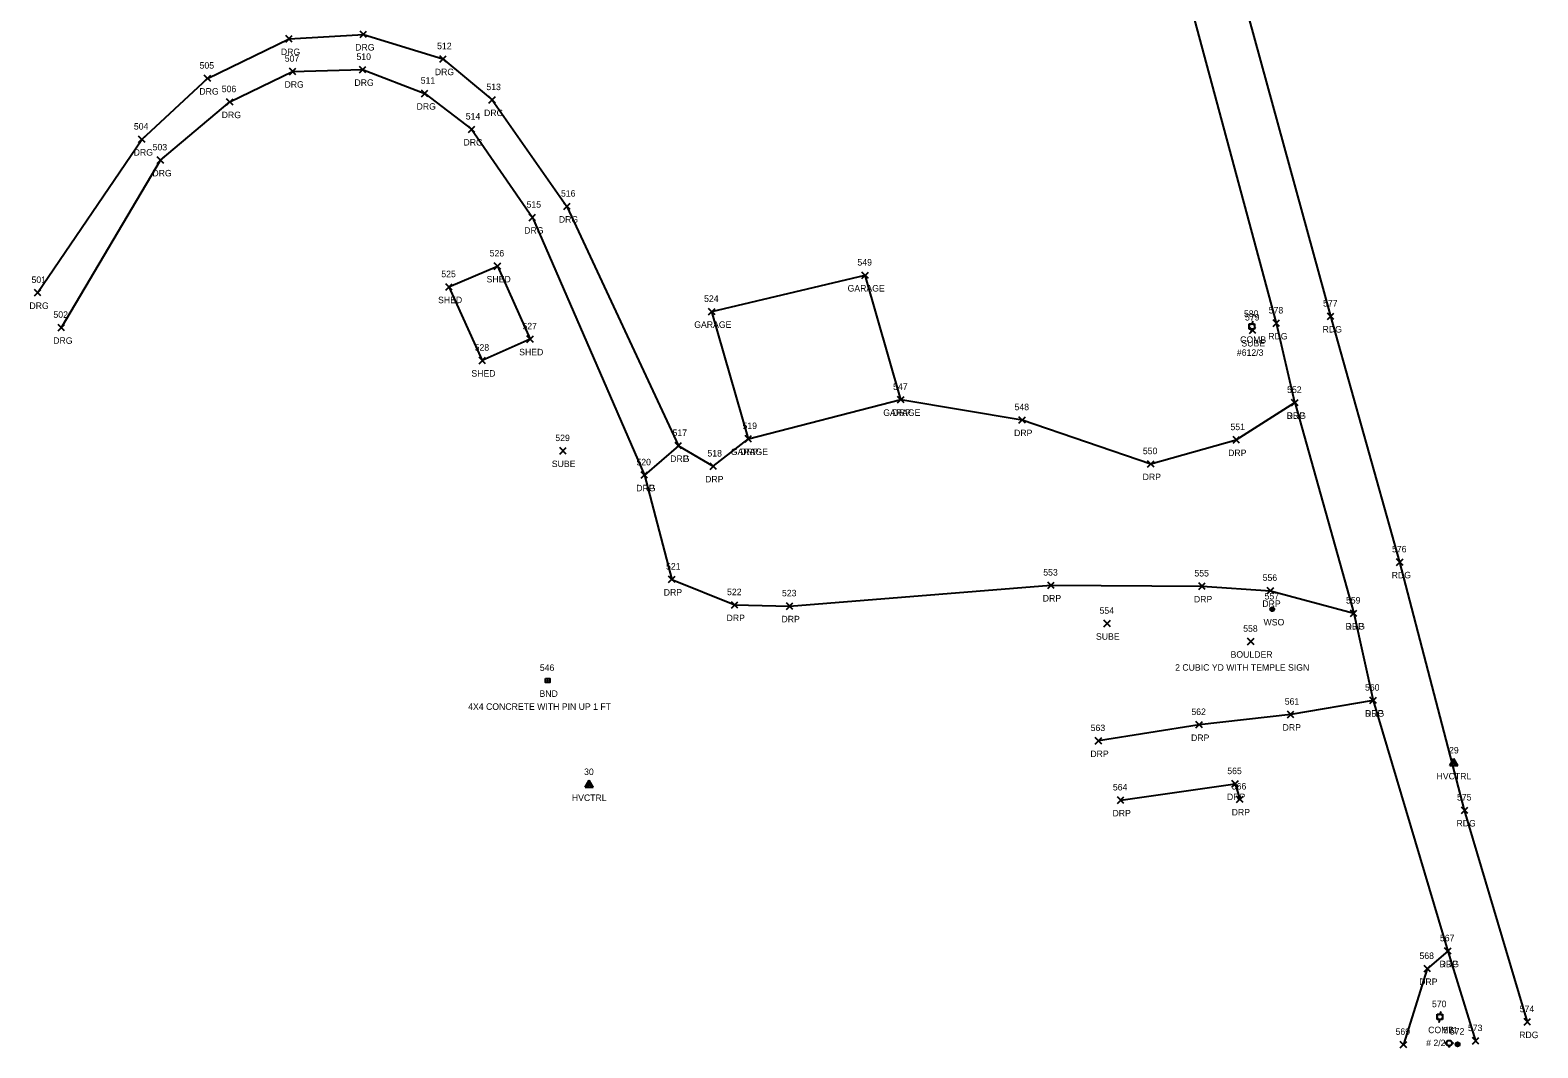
# Model space of a CAD drawing. Extents: x 1845178 to 1850791, y 714586 to 722436.
# Drawn here: x 1850260.9 to 1850725.1, y 716482.1 to 716795.6 of the extents above; entities that cross this region are included whole.
import ezdxf

# ---------------------------------------------------------------- set-up
doc = ezdxf.new("R2010")
doc.units = 0
for name, color, linetype in [('C_A', 7, 'Continuous'), ('C_I', 7, 'Continuous'), ('CPSM', 7, 'Continuous'), ('L_A', 7, 'Continuous'), ('L_C', 7, 'Continuous'), ('L_I', 7, 'Continuous'), ('L_TIC', 7, 'Continuous'), ('LBC', 7, 'Continuous'), ('Level 18', 7, 'Continuous'), ('M_A', 7, 'Continuous'), ('M_C', 7, 'Continuous'), ('M_I', 7, 'Continuous'), ('P_A', 7, 'Continuous'), ('P_I', 7, 'Continuous'), ('P_TIC', 7, 'Continuous'), ('PEU', 7, 'Continuous'), ('R_A', 7, 'Continuous'), ('R_I', 7, 'Continuous'), ('R_TIC', 7, 'Continuous'), ('RDG', 7, 'Continuous'), ('RDP', 7, 'Continuous'), ('U_A', 7, 'Continuous'), ('U_C', 7, 'Continuous'), ('U_I', 7, 'Continuous'), ('U_TIC', 7, 'Continuous'), ('UP', 7, 'Continuous'), ('UWFH', 7, 'Continuous'), ('UWV', 7, 'Continuous')]:
    doc.layers.add(name, color=color, linetype=linetype)

msp = doc.modelspace()

# ---------------------------------------------------------------- linework, layer by layer
at = {"layer": 'CPSM'}
for p, q in [((1850698.01, 716569.06), (1850699.26, 716571.23)), ((1850698.01, 716569.06), (1850699.26, 716569.79)), ((1850700.51, 716569.06), (1850699.26, 716571.23)), ((1850699.26, 716569.79), (1850699.26, 716571.23)), ((1850699.26, 716569.79), (1850699.26, 716569.79)), ((1850699.26, 716569.79), (1850700.51, 716569.06)), ((1850431.76, 716562.42), (1850433.01, 716564.59)), ((1850434.26, 716562.42), (1850433.01, 716564.59)), ((1850433.01, 716563.15), (1850433.01, 716564.59)), ((1850698.01, 716569.06), (1850700.51, 716569.06)), ((1850431.76, 716562.42), (1850433.01, 716563.15)), ((1850431.76, 716562.42), (1850434.26, 716562.42)), ((1850433.01, 716563.15), (1850433.01, 716563.15)), ((1850433.01, 716563.15), (1850434.26, 716562.42))]:
    msp.add_line(p, q, dxfattribs=at)
at = {"layer": 'L_TIC'}
for points in [[(1850403.81, 716721.87), (1850405.81, 716723.87)], [(1850405.81, 716721.87), (1850403.81, 716723.87)], [(1850517, 716719.07), (1850519, 716721.07)], [(1850519, 716719.07), (1850517, 716721.07)], [(1850517, 716719.07), (1850519, 716721.07)], [(1850519, 716719.07), (1850517, 716721.07)], [(1850388.86, 716715.48), (1850390.86, 716717.48)], [(1850390.86, 716715.48), (1850388.86, 716717.48)], [(1850388.86, 716715.48), (1850390.86, 716717.48)], [(1850390.86, 716715.48), (1850388.86, 716717.48)], [(1850469.78, 716707.88), (1850471.78, 716709.88)], [(1850471.78, 716707.88), (1850469.78, 716709.88)], [(1850413.85, 716699.42), (1850415.85, 716701.42)], [(1850415.85, 716699.42), (1850413.85, 716701.42)], [(1850399.13, 716692.85), (1850401.13, 716694.85)], [(1850401.13, 716692.85), (1850399.13, 716694.85)], [(1850399.13, 716692.85), (1850401.13, 716694.85)], [(1850401.13, 716692.85), (1850399.13, 716694.85)], [(1850527.99, 716680.77), (1850529.99, 716682.77)], [(1850529.99, 716680.77), (1850527.99, 716682.77)], [(1850481.05, 716668.71), (1850483.05, 716670.71)], [(1850483.05, 716668.71), (1850481.05, 716670.71)], [(1850481.05, 716668.71), (1850483.05, 716670.71)], [(1850483.05, 716668.71), (1850481.05, 716670.71)], [(1850635.77, 716606.28), (1850637.77, 716608.28)], [(1850637.77, 716606.28), (1850635.77, 716608.28)]]:
    msp.add_lwpolyline(points, dxfattribs=at)
at = {"layer": 'LBC'}
for points in [[(1850389.86, 716716.48), (1850404.81, 716722.87), (1850414.85, 716700.42), (1850400.13, 716693.85)], [(1850482.05, 716669.71), (1850470.78, 716708.88), (1850518, 716720.07)], [(1850482.05, 716669.71), (1850528.99, 716681.77), (1850518, 716720.07)], [(1850389.86, 716716.48), (1850400.13, 716693.85)]]:
    msp.add_lwpolyline(points, dxfattribs=at)
at = {"layer": 'Level 18'}
msp.add_lwpolyline([(1850419.63, 716595.85), (1850420.88, 716595.85), (1850420.88, 716594.6), (1850419.63, 716594.6)], close=True, dxfattribs=at)
msp.add_circle((1850420.25, 716595.22), 0.0833, dxfattribs=at)
at = {"layer": 'P_TIC'}
for points in [[(1850643.64, 716704.31), (1850645.64, 716706.31)], [(1850645.64, 716704.31), (1850643.64, 716706.31)], [(1850660.37, 716706.44), (1850662.37, 716708.44)], [(1850662.37, 716706.44), (1850660.37, 716708.44)], [(1850649.3, 716679.85), (1850651.3, 716681.85)], [(1850651.3, 716679.85), (1850649.3, 716681.85)], [(1850649.3, 716679.85), (1850651.3, 716681.85)], [(1850651.3, 716679.85), (1850649.3, 716681.85)], [(1850681.65, 716630.73), (1850683.65, 716632.73)], [(1850683.65, 716630.73), (1850681.65, 716632.73)], [(1850667.43, 716614.96), (1850669.43, 716616.96)], [(1850669.43, 716614.96), (1850667.43, 716616.96)], [(1850673.42, 716588.13), (1850675.42, 716590.13)], [(1850675.42, 716588.13), (1850673.42, 716590.13)], [(1850701.6, 716554.29), (1850703.6, 716556.29)], [(1850703.6, 716554.29), (1850701.6, 716556.29)], [(1850696.4, 716510.94), (1850698.4, 716512.94)], [(1850698.4, 716510.94), (1850696.4, 716512.94)], [(1850720.91, 716489.1), (1850722.91, 716491.1)], [(1850722.91, 716489.1), (1850720.91, 716491.1)], [(1850704.97, 716483.27), (1850706.97, 716485.27)], [(1850706.97, 716483.27), (1850704.97, 716485.27)]]:
    msp.add_lwpolyline(points, dxfattribs=at)
at = {"layer": 'PEU'}
for points in [[(1850721.91, 716490.1), (1850702.6, 716555.29), (1850682.65, 716631.73), (1850661.37, 716707.44), (1850629.08, 716825.6), (1850588.58, 716973.12)], [(1850650.3, 716680.85), (1850644.64, 716705.31), (1850614.03, 716818.99), (1850573.49, 716966.74)], [(1850650.3, 716680.85), (1850668.43, 716615.96), (1850674.42, 716589.13), (1850697.4, 716511.94), (1850705.97, 716484.27)]]:
    msp.add_lwpolyline(points, dxfattribs=at)
at = {"layer": 'R_TIC'}
for points in [[(1850339.61, 716791.9), (1850341.61, 716793.9)], [(1850341.61, 716791.9), (1850339.61, 716793.9)], [(1850362.5, 716793.29), (1850364.5, 716795.29)], [(1850364.5, 716793.29), (1850362.5, 716795.29)], [(1850387.01, 716785.71), (1850389.01, 716787.71)], [(1850389.01, 716785.71), (1850387.01, 716787.71)], [(1850340.73, 716781.85), (1850342.73, 716783.85)], [(1850342.73, 716781.85), (1850340.73, 716783.85)], [(1850362.27, 716782.42), (1850364.27, 716784.42)], [(1850364.27, 716782.42), (1850362.27, 716784.42)], [(1850314.51, 716779.72), (1850316.51, 716781.72)], [(1850316.51, 716779.72), (1850314.51, 716781.72)], [(1850321.39, 716772.47), (1850323.39, 716774.47)], [(1850323.39, 716772.47), (1850321.39, 716774.47)], [(1850381.39, 716775.08), (1850383.39, 716777.08)], [(1850383.39, 716775.08), (1850381.39, 716777.08)], [(1850402.17, 716773.11), (1850404.17, 716775.11)], [(1850404.17, 716773.11), (1850402.17, 716775.11)], [(1850395.84, 716764.04), (1850397.84, 716766.04)], [(1850397.84, 716764.04), (1850395.84, 716766.04)], [(1850294.28, 716760.94), (1850296.28, 716762.94)], [(1850296.28, 716760.94), (1850294.28, 716762.94)], [(1850300.05, 716754.54), (1850302.05, 716756.54)], [(1850302.05, 716754.54), (1850300.05, 716756.54)], [(1850425.2, 716740.29), (1850427.2, 716742.29)], [(1850427.2, 716740.29), (1850425.2, 716742.29)], [(1850414.54, 716736.89), (1850416.54, 716738.89)], [(1850416.54, 716736.89), (1850414.54, 716738.89)], [(1850262.19, 716713.71), (1850264.19, 716715.71)], [(1850264.19, 716713.71), (1850262.19, 716715.71)], [(1850269.52, 716702.96), (1850271.52, 716704.96)], [(1850271.52, 716702.96), (1850269.52, 716704.96)], [(1850527.99, 716680.77), (1850529.99, 716682.77)], [(1850529.99, 716680.77), (1850527.99, 716682.77)], [(1850649.3, 716679.85), (1850651.3, 716681.85)], [(1850651.3, 716679.85), (1850649.3, 716681.85)], [(1850565.37, 716674.52), (1850567.37, 716676.52)], [(1850567.37, 716674.52), (1850565.37, 716676.52)], [(1850459.49, 716666.58), (1850461.49, 716668.58)], [(1850461.49, 716666.58), (1850459.49, 716668.58)], [(1850459.49, 716666.58), (1850461.49, 716668.58)], [(1850461.49, 716666.58), (1850459.49, 716668.58)], [(1850459.49, 716666.58), (1850461.49, 716668.58)], [(1850461.49, 716666.58), (1850459.49, 716668.58)], [(1850481.05, 716668.71), (1850483.05, 716670.71)], [(1850483.05, 716668.71), (1850481.05, 716670.71)], [(1850631.28, 716668.37), (1850633.28, 716670.37)], [(1850633.28, 716668.37), (1850631.28, 716670.37)], [(1850470.25, 716660.25), (1850472.25, 716662.25)], [(1850472.25, 716660.25), (1850470.25, 716662.25)], [(1850604.96, 716660.97), (1850606.96, 716662.97)], [(1850606.96, 716660.97), (1850604.96, 716662.97)], [(1850449.03, 716657.54), (1850451.03, 716659.54)], [(1850451.03, 716657.54), (1850449.03, 716659.54)], [(1850449.03, 716657.54), (1850451.03, 716659.54)], [(1850451.03, 716657.54), (1850449.03, 716659.54)], [(1850457.5, 716625.42), (1850459.5, 716627.42)], [(1850459.5, 716625.42), (1850457.5, 716627.42)], [(1850574.21, 716623.58), (1850576.21, 716625.58)], [(1850576.21, 716623.58), (1850574.21, 716625.58)], [(1850620.75, 716623.3), (1850622.75, 716625.3)], [(1850622.75, 716623.3), (1850620.75, 716625.3)], [(1850641.81, 716621.93), (1850643.81, 716623.93)], [(1850643.81, 716621.93), (1850641.81, 716623.93)], [(1850476.85, 716617.54), (1850478.85, 716619.54)], [(1850478.85, 716617.54), (1850476.85, 716619.54)], [(1850493.75, 716617.18), (1850495.75, 716619.18)], [(1850495.75, 716617.18), (1850493.75, 716619.18)], [(1850667.43, 716614.96), (1850669.43, 716616.96)], [(1850669.43, 716614.96), (1850667.43, 716616.96)], [(1850673.42, 716588.13), (1850675.42, 716590.13)], [(1850675.42, 716588.13), (1850673.42, 716590.13)], [(1850648.05, 716583.81), (1850650.05, 716585.81)], [(1850650.05, 716583.81), (1850648.05, 716585.81)], [(1850619.86, 716580.63), (1850621.86, 716582.63)], [(1850621.86, 716580.63), (1850619.86, 716582.63)], [(1850588.86, 716575.68), (1850590.86, 716577.68)], [(1850590.86, 716575.68), (1850588.86, 716577.68)], [(1850630.92, 716562.41), (1850632.92, 716564.41)], [(1850632.92, 716562.41), (1850630.92, 716564.41)], [(1850595.69, 716557.39), (1850597.69, 716559.39)], [(1850597.69, 716557.39), (1850595.69, 716559.39)], [(1850632.37, 716557.68), (1850634.37, 716559.68)], [(1850634.37, 716557.68), (1850632.37, 716559.68)], [(1850696.4, 716510.94), (1850698.4, 716512.94)], [(1850698.4, 716510.94), (1850696.4, 716512.94)], [(1850690.1, 716505.48), (1850692.1, 716507.48)], [(1850692.1, 716505.48), (1850690.1, 716507.48)], [(1850682.75, 716482.11), (1850684.75, 716484.11)], [(1850684.75, 716482.11), (1850682.75, 716484.11)]]:
    msp.add_lwpolyline(points, dxfattribs=at)
at = {"layer": 'RDG'}
for points in [[(1850263.19, 716714.71), (1850295.28, 716761.94), (1850315.51, 716780.72), (1850340.61, 716792.9), (1850363.5, 716794.29), (1850388.01, 716786.71), (1850403.17, 716774.11), (1850426.2, 716741.29), (1850460.49, 716667.58)], [(1850270.52, 716703.96), (1850301.05, 716755.54), (1850322.39, 716773.47), (1850341.73, 716782.85), (1850363.27, 716783.42), (1850382.39, 716776.08), (1850396.84, 716765.04), (1850415.54, 716737.89), (1850450.03, 716658.54)]]:
    msp.add_lwpolyline(points, dxfattribs=at)
at = {"layer": 'RDP'}
for points in [[(1850528.99, 716681.77), (1850566.37, 716675.52), (1850605.96, 716661.97), (1850632.28, 716669.37), (1850650.3, 716680.85)], [(1850460.49, 716667.58), (1850450.03, 716658.54), (1850458.5, 716626.42), (1850477.85, 716618.54), (1850494.75, 716618.18), (1850575.21, 716624.58), (1850621.75, 716624.3), (1850642.81, 716622.93), (1850668.43, 716615.96)], [(1850460.49, 716667.58), (1850471.25, 716661.25), (1850482.05, 716669.71)], [(1850674.42, 716589.13), (1850649.05, 716584.81), (1850620.86, 716581.63), (1850589.86, 716576.68)], [(1850596.69, 716558.39), (1850631.92, 716563.41), (1850633.37, 716558.68)], [(1850697.4, 716511.94), (1850691.1, 716506.48), (1850683.75, 716483.11)]]:
    msp.add_lwpolyline(points, dxfattribs=at)
at = {"layer": 'U_TIC'}
for points in [[(1850636.33, 716702.14), (1850638.33, 716704.14)], [(1850638.33, 716702.14), (1850636.33, 716704.14)], [(1850423.98, 716665), (1850425.98, 716667)], [(1850425.98, 716665), (1850423.98, 716667)], [(1850591.55, 716611.81), (1850593.55, 716613.81)], [(1850593.55, 716611.81), (1850591.55, 716613.81)]]:
    msp.add_lwpolyline(points, dxfattribs=at)
at = {"layer": 'UP'}
for p, q in [((1850636.25, 716703.43), (1850636.25, 716705.09)), ((1850636.25, 716705.09), (1850637.92, 716705.09)), ((1850637.34, 716705.93), (1850637.09, 716705.09)), ((1850637.09, 716704.26), (1850637.09, 716704.26)), ((1850637.92, 716705.09), (1850637.92, 716703.43)), ((1850637.92, 716703.43), (1850636.25, 716703.43)), ((1850636.84, 716702.59), (1850637.09, 716703.43)), ((1850694.15, 716490.79), (1850694.15, 716492.46)), ((1850694.15, 716492.46), (1850695.82, 716492.46)), ((1850695.82, 716490.79), (1850694.15, 716490.79)), ((1850694.73, 716489.96), (1850694.98, 716490.79)), ((1850695.23, 716493.29), (1850694.98, 716492.46)), ((1850694.98, 716491.63), (1850694.98, 716491.63)), ((1850695.82, 716492.46), (1850695.82, 716490.79))]:
    msp.add_line(p, q, dxfattribs=at)
for centre in [(1850637.09, 716704.26), (1850694.98, 716491.63)]:
    msp.add_circle(centre, 0.833, dxfattribs=at)
at = {"layer": 'UWFH'}
msp.add_line((1850697.85, 716483.56), (1850697.85, 716483.56), dxfattribs=at)
for centre, radius in [((1850696.85, 716483.56), 0.167), ((1850697.85, 716483.56), 0.833), ((1850697.85, 716482.56), 0.167), ((1850698.85, 716483.56), 0.167)]:
    msp.add_circle(centre, radius, dxfattribs=at)
at = {"layer": 'UWV'}
for centre, radius in [((1850643.35, 716617.22), 0.625), ((1850643.35, 716617.22), 0.0833), ((1850700.42, 716483.2), 0.625), ((1850700.42, 716483.2), 0.0833)]:
    msp.add_circle(centre, radius, dxfattribs=at)

# ---------------------------------------------------------------- texts
at = {"layer": 'C_A'}
for p in [(1850693.95, 716564.79), (1850427.7, 716558.15)]:
    msp.add_text('HVCTRL', height=2, dxfattribs=at).set_placement(p)
at = {"layer": 'C_I'}
for s, p in [('29', (1850697.79, 716572.79)), ('30', (1850431.46, 716566.15))]:
    msp.add_text(s, height=2, dxfattribs=at).set_placement(p)
at = {"layer": 'L_A'}
for s, p in [('SHED', (1850401.45, 716717.87)), ('SHED', (1850386.5, 716711.48)), ('SHED', (1850386.5, 716711.48)), ('GARAGE', (1850512.6, 716715.07)), ('GARAGE', (1850512.6, 716715.07)), ('GARAGE', (1850465.38, 716703.88)), ('SHED', (1850411.48, 716695.42)), ('SHED', (1850396.77, 716688.85)), ('SHED', (1850396.77, 716688.85)), ('GARAGE', (1850523.58, 716676.77)), ('GARAGE', (1850476.64, 716664.71)), ('GARAGE', (1850476.64, 716664.71)), ('BOULDER', (1850630.53, 716602.28))]:
    msp.add_text(s, height=2, dxfattribs=at).set_placement(p)
at = {"layer": 'L_C'}
msp.add_text('2 CUBIC YD WITH TEMPLE SIGN', height=2, dxfattribs=at).set_placement((1850613.45, 716598.28))
at = {"layer": 'L_I'}
for s, p in [('526', (1850402.4, 716725.87)), ('549', (1850515.63, 716723.07)), ('549', (1850515.63, 716723.07)), ('525', (1850387.5, 716719.48)), ('525', (1850387.5, 716719.48)), ('524', (1850468.42, 716711.88)), ('527', (1850412.48, 716703.42)), ('528', (1850397.77, 716696.85)), ('528', (1850397.77, 716696.85)), ('547', (1850526.62, 716684.77)), ('519', (1850480.24, 716672.71)), ('519', (1850480.24, 716672.71)), ('558', (1850634.41, 716610.28))]:
    msp.add_text(s, height=2, dxfattribs=at).set_placement(p)
at = {"layer": 'M_A'}
msp.add_text('BND', height=2, dxfattribs=at).set_placement((1850417.74, 716590.22))
at = {"layer": 'M_C'}
msp.add_text('4X4 CONCRETE WITH PIN UP 1 FT', height=2, dxfattribs=at).set_placement((1850395.77, 716586.22))
at = {"layer": 'M_I'}
msp.add_text('546', height=2, dxfattribs=at).set_placement((1850417.84, 716598.22))
at = {"layer": 'P_A'}
for p in [(1850658.86, 716702.44), (1850642.13, 716700.31), (1850647.79, 716675.85), (1850647.79, 716675.85), (1850680.13, 716626.73), (1850665.92, 716610.96), (1850671.91, 716584.13), (1850700.09, 716550.29), (1850694.89, 716506.94), (1850719.39, 716485.1)]:
    msp.add_text('RDG', height=2, dxfattribs=at).set_placement(p)
at = {"layer": 'P_I'}
for s, p in [('578', (1850642.28, 716708.31)), ('577', (1850659.01, 716710.44)), ('552', (1850647.94, 716683.85)), ('552', (1850647.94, 716683.85)), ('576', (1850680.23, 716634.73)), ('559', (1850666.06, 716618.96)), ('560', (1850671.92, 716592.13)), ('575', (1850700.24, 716558.29)), ('567', (1850694.99, 716514.94)), ('574', (1850719.54, 716493.1)), ('573', (1850703.61, 716487.27))]:
    msp.add_text(s, height=2, dxfattribs=at).set_placement(p)
at = {"layer": 'R_A'}
for s, p in [('DRG', (1850338.1, 716787.9)), ('DRG', (1850360.99, 716789.29)), ('DRG', (1850385.5, 716781.71)), ('DRG', (1850339.22, 716777.85)), ('DRG', (1850360.75, 716778.42)), ('DRG', (1850313, 716775.72)), ('DRG', (1850319.88, 716768.47)), ('DRG', (1850379.88, 716771.08)), ('DRG', (1850400.66, 716769.11)), ('DRG', (1850394.33, 716760.04)), ('DRG', (1850292.77, 716756.94)), ('DRG', (1850298.54, 716750.54)), ('DRG', (1850423.69, 716736.29)), ('DRG', (1850413.03, 716732.89)), ('DRG', (1850260.68, 716709.71)), ('DRG', (1850268, 716698.96)), ('DRP', (1850526.47, 716676.77)), ('DRP', (1850647.79, 716675.85)), ('DRP', (1850563.86, 716670.52)), ('DRG', (1850457.98, 716662.58)), ('DRP', (1850457.98, 716662.58)), ('DRP', (1850457.98, 716662.58)), ('DRP', (1850479.53, 716664.71)), ('DRP', (1850629.77, 716664.37)), ('DRP', (1850468.74, 716656.25)), ('DRP', (1850603.45, 716656.97)), ('DRG', (1850447.52, 716653.54)), ('DRP', (1850447.52, 716653.54)), ('DRP', (1850455.99, 716621.42)), ('DRP', (1850572.7, 716619.58)), ('DRP', (1850619.24, 716619.3)), ('DRP', (1850640.3, 716617.93)), ('DRP', (1850475.34, 716613.54)), ('DRP', (1850492.24, 716613.18)), ('DRP', (1850665.92, 716610.96)), ('DRP', (1850671.91, 716584.13)), ('DRP', (1850618.35, 716576.63)), ('DRP', (1850646.54, 716579.81)), ('DRP', (1850587.35, 716571.68)), ('DRP', (1850629.41, 716558.41)), ('DRP', (1850594.17, 716553.39)), ('DRP', (1850630.86, 716553.68)), ('DRP', (1850694.89, 716506.94)), ('DRP', (1850688.59, 716501.48))]:
    msp.add_text(s, height=2, dxfattribs=at).set_placement(p)
at = {"layer": 'R_I'}
for s, p in [('507', (1850339.29, 716785.85)), ('510', (1850361.38, 716786.42)), ('512', (1850386.21, 716789.71)), ('505', (1850313.07, 716783.72)), ('506', (1850319.9, 716776.47)), ('511', (1850381.16, 716779.08)), ('513', (1850401.38, 716777.11)), ('514', (1850395.04, 716768.04)), ('504', (1850292.84, 716764.94)), ('503', (1850298.61, 716758.54)), ('516', (1850424.35, 716744.29)), ('515', (1850413.75, 716740.89)), ('501', (1850261.32, 716717.71)), ('502', (1850268.07, 716706.96)), ('547', (1850526.62, 716684.77)), ('552', (1850647.94, 716683.85)), ('548', (1850564.01, 716678.52)), ('517', (1850458.69, 716670.58)), ('517', (1850458.69, 716670.58)), ('517', (1850458.69, 716670.58)), ('519', (1850480.24, 716672.71)), ('551', (1850630.49, 716672.37)), ('550', (1850603.52, 716664.97)), ('520', (1850447.58, 716661.54)), ('520', (1850447.58, 716661.54)), ('518', (1850469.45, 716664.25)), ('521', (1850456.7, 716629.42)), ('553', (1850572.85, 716627.58)), ('555', (1850619.39, 716627.3)), ('556', (1850640.4, 716625.93)), ('522', (1850475.49, 716621.54)), ('523', (1850492.39, 716621.18)), ('559', (1850666.06, 716618.96)), ('560', (1850671.92, 716592.13)), ('561', (1850647.21, 716587.81)), ('562', (1850618.46, 716584.63)), ('563', (1850587.45, 716579.68)), ('565', (1850629.51, 716566.41)), ('564', (1850594.28, 716561.39)), ('566', (1850630.91, 716561.68)), ('567', (1850694.99, 716514.94)), ('568', (1850688.69, 716509.48)), ('569', (1850681.33, 716486.11))]:
    msp.add_text(s, height=2, dxfattribs=at).set_placement(p)
at = {"layer": 'U_A'}
for s, p in [('COMB', (1850633.47, 716699.26)), ('SUBE', (1850633.86, 716698.14)), ('SUBE', (1850421.52, 716661)), ('WSO', (1850640.68, 716612.22)), ('SUBE', (1850589.08, 716607.81)), ('COMB', (1850691.37, 716486.63))]:
    msp.add_text(s, height=2, dxfattribs=at).set_placement(p)
at = {"layer": 'U_C'}
for s, p in [('#612/3', (1850632.47, 716695.26)), ('# 2/2', (1850690.75, 716482.63))]:
    msp.add_text(s, height=2, dxfattribs=at).set_placement(p)
at = {"layer": 'U_I'}
for s, p in [('580', (1850634.64, 716707.26)), ('579', (1850634.96, 716706.14)), ('529', (1850422.61, 716669)), ('557', (1850640.99, 716620.22)), ('554', (1850590.18, 716615.81)), ('570', (1850692.53, 716494.63)), ('571', (1850696.05, 716486.56)), ('572', (1850698.06, 716486.2))]:
    msp.add_text(s, height=2, dxfattribs=at).set_placement(p)

doc.saveas('drawing.dxf')
